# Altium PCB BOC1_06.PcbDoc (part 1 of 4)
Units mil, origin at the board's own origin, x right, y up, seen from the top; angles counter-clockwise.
Board outline 7900 x 6500 mil, 2 copper layers (Top Layer, Bottom Layer); 312 components, 413 nets, 1710 pads, 368 vias.
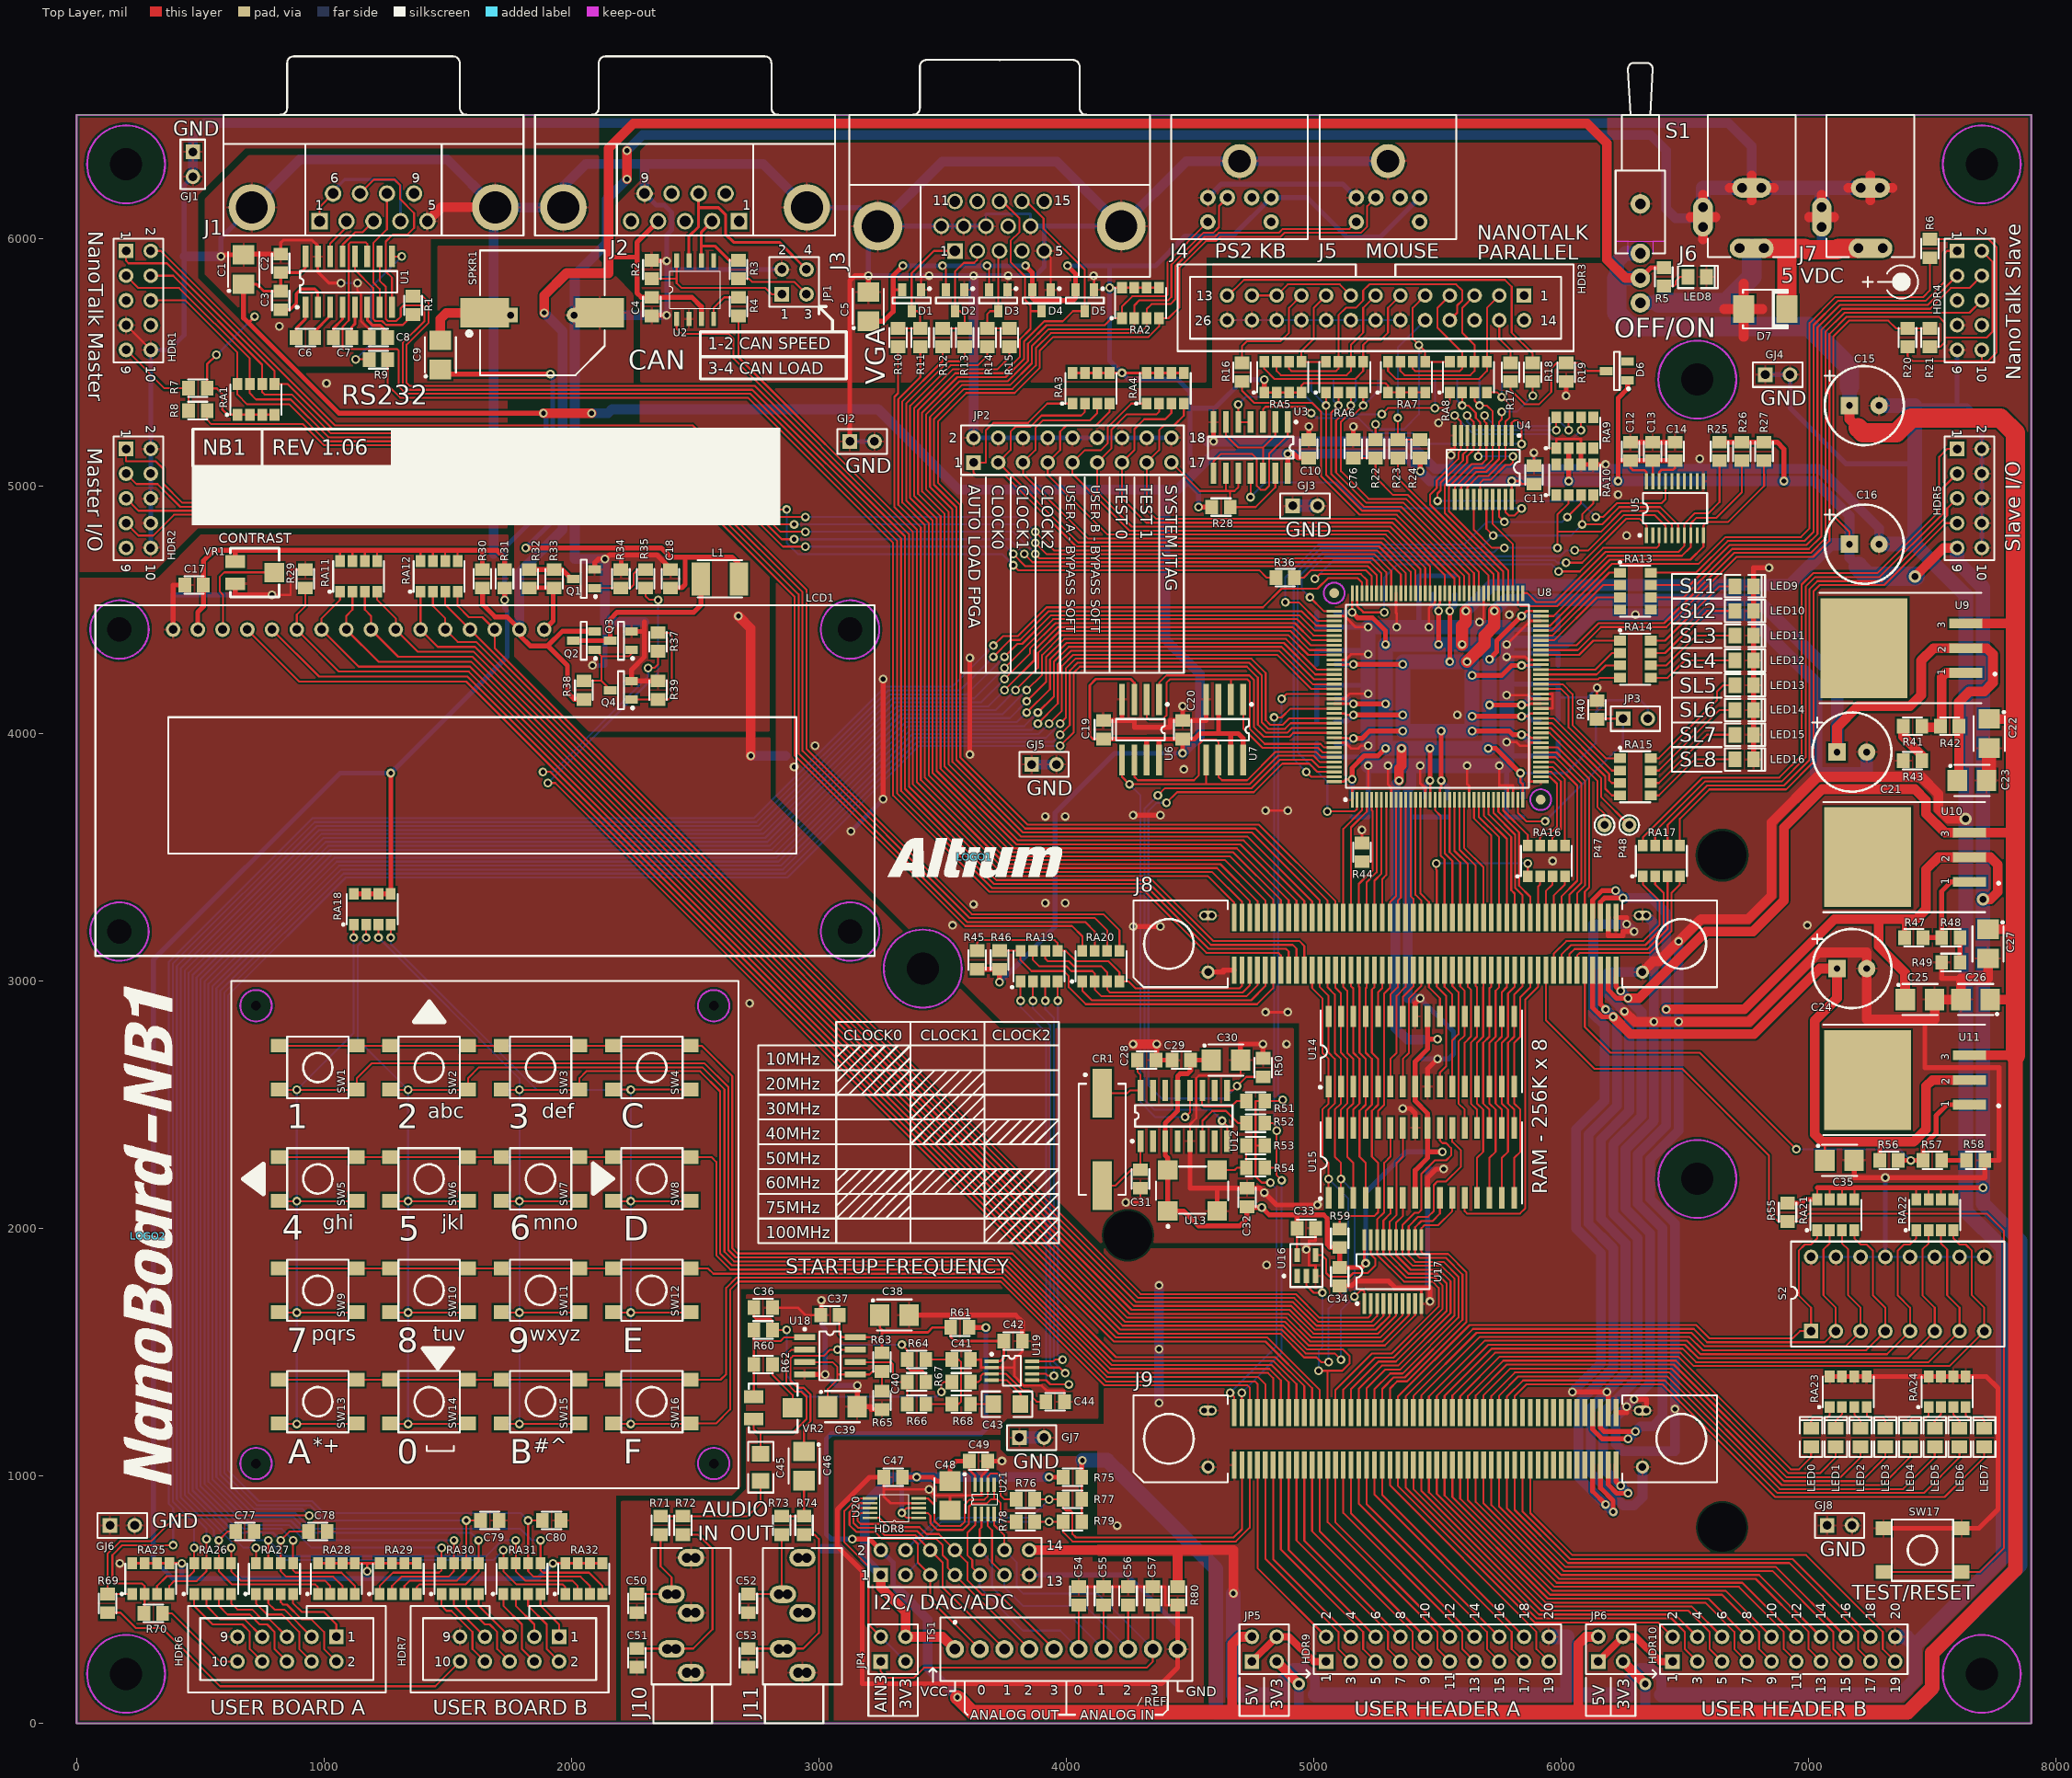
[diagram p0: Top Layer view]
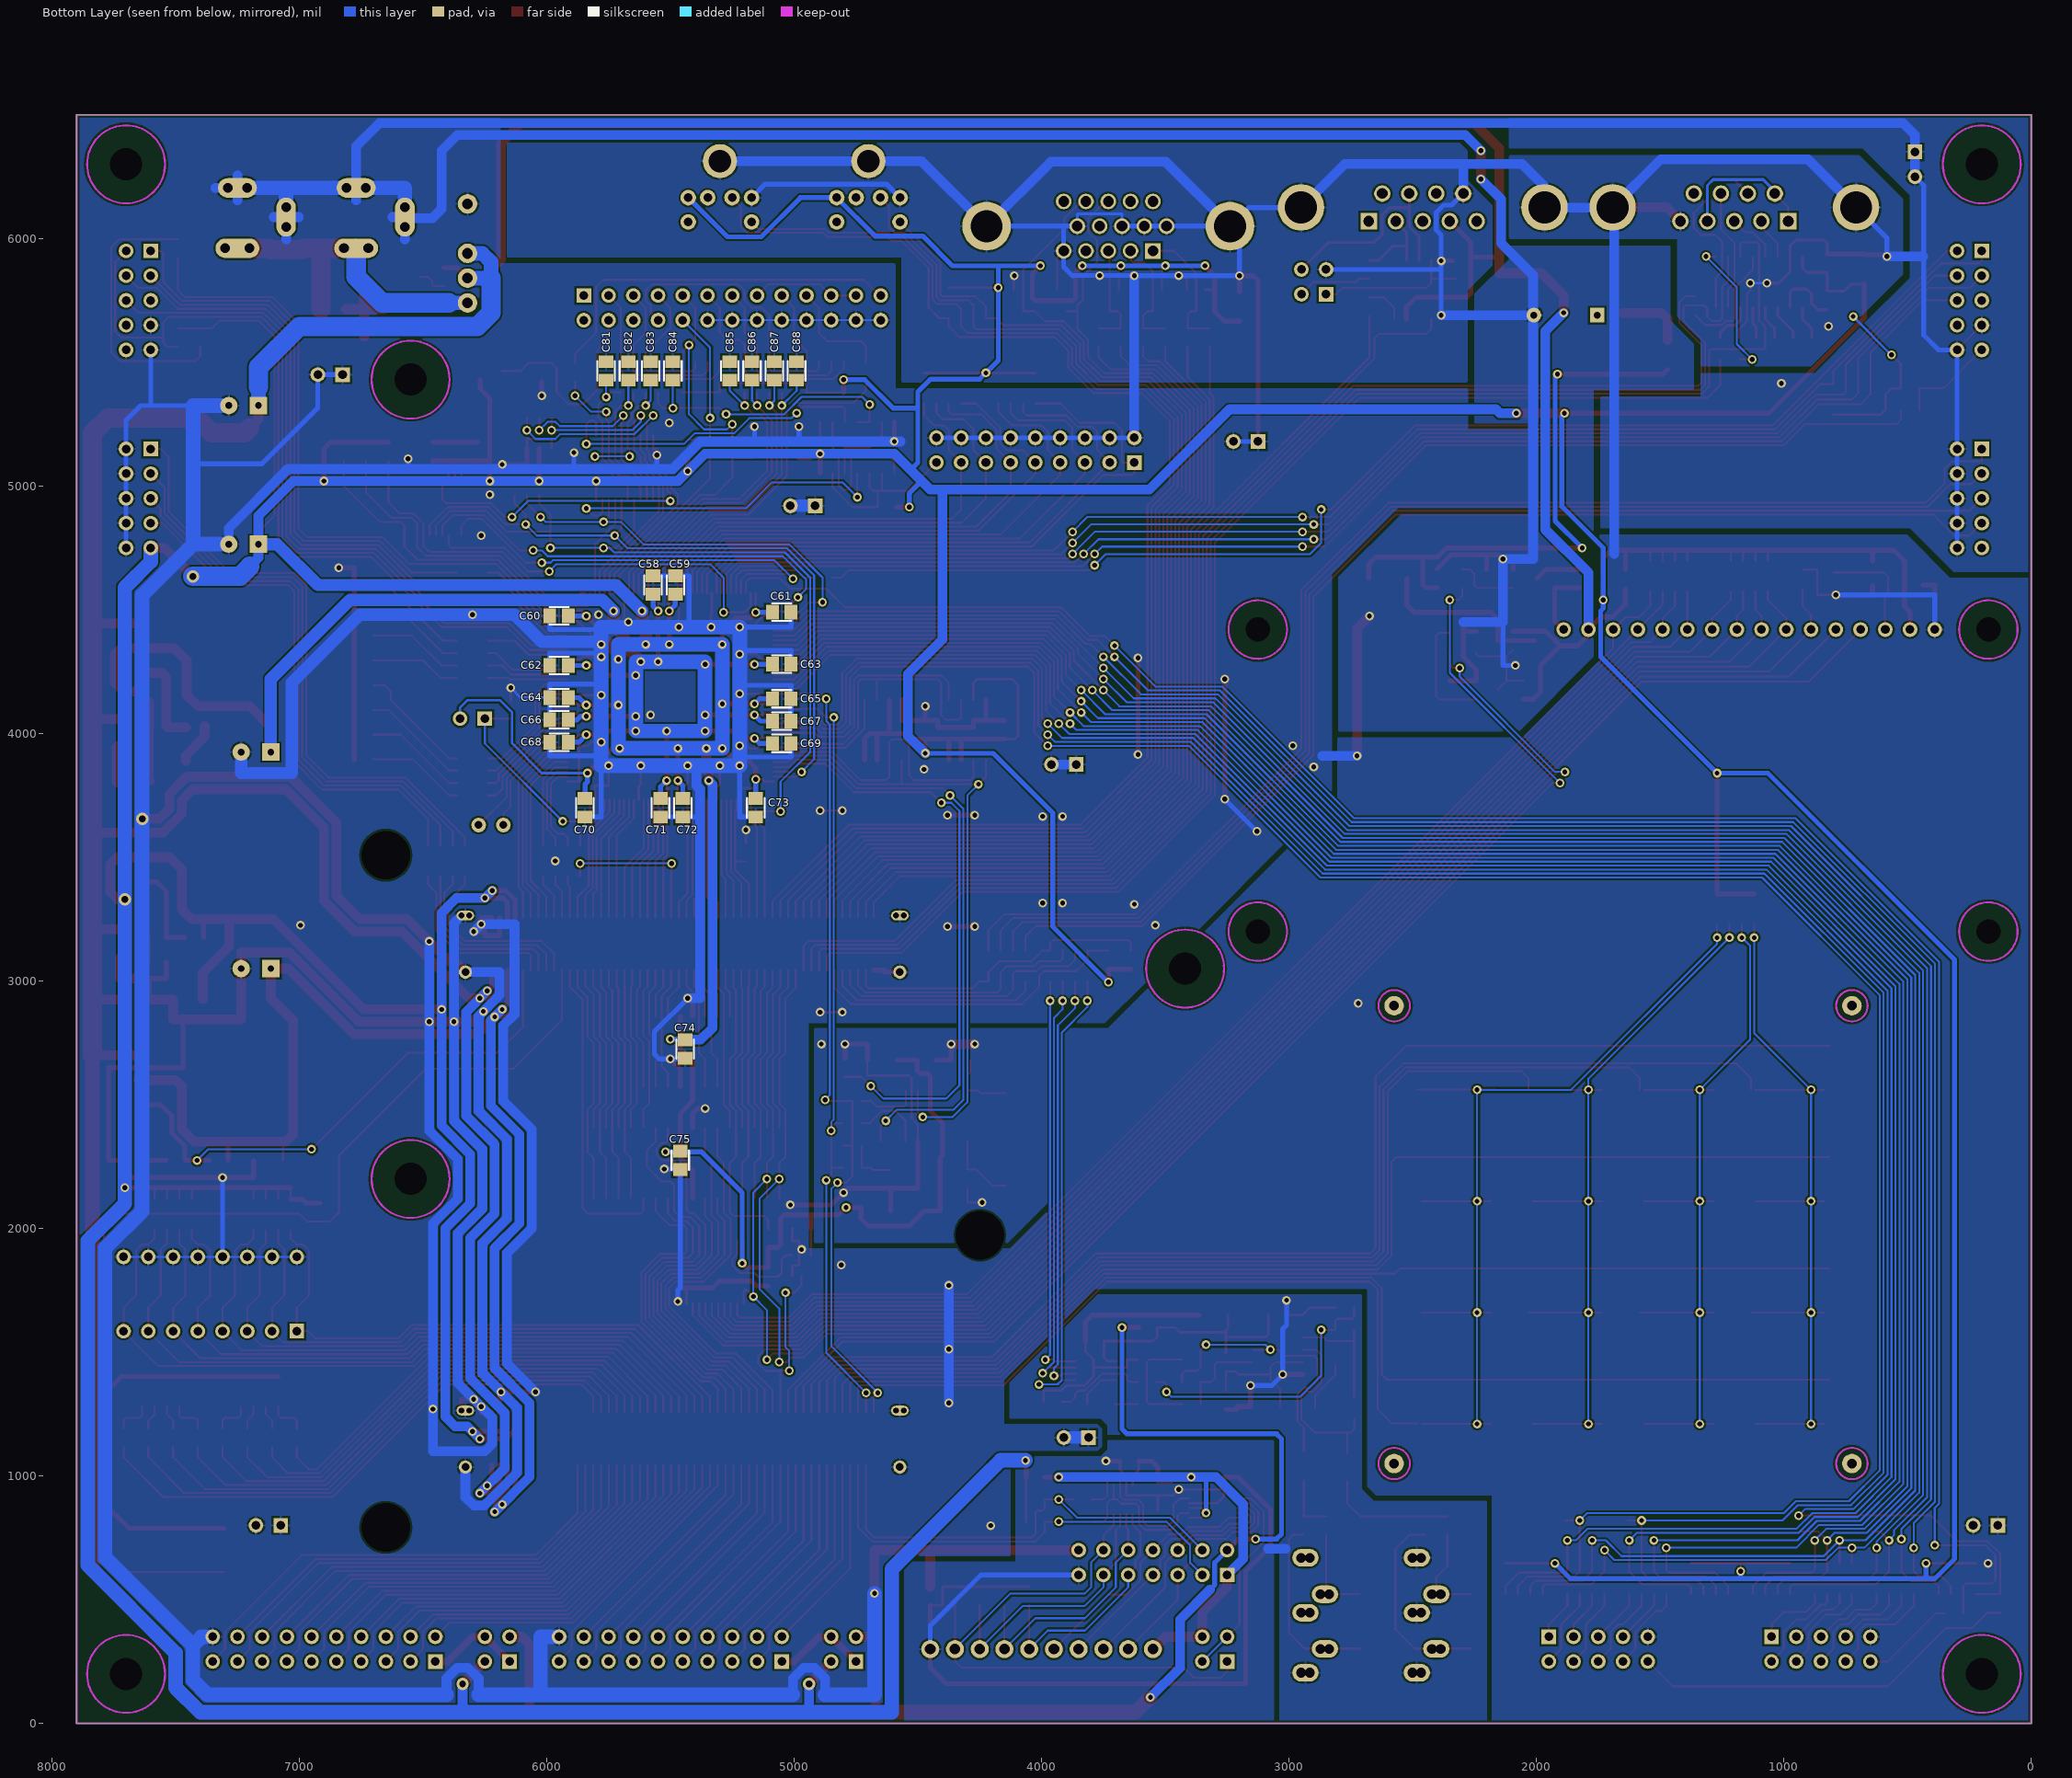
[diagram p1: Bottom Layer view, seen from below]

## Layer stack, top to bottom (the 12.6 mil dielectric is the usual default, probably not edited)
Top Layer: signal copper 1.4
Dielectric: core 12.6, FR-4, Dk 4.8
Bottom Layer: signal copper 1.4

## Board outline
0,0 7900,0 7900,6500 0,6500

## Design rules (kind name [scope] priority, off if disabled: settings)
Clearance [All] p1: gap=7.87
ComponentClearance LEDComponentClearance [HasFootprint('SMD _LED') vs HasFootprint('SMD _LED')] p1: gap=1.18 collisioncheckmode=3 verticalgap=10 showdistances=FALSE
ComponentClearance ComponentClearance_General [Not InComponent('LCD1') vs Not InComponentClass('Under_LCD1')] p2: gap=7.87 collisioncheckmode=3 verticalgap=10 showdistances=FALSE
ComponentClearance ComponentClearance_Default [All] p3 off: gap=7.87 collisioncheckmode=3 verticalgap=10 showdistances=FALSE
FabricationTestPointUsage TestPointUsage [All] p1 off: valid=0 allowmultiple=FALSE
FabricationTestpoint Testpoint [All] p1 off: side=3 testpointundercomponent=TRUE minsize=40 maxsize=100 preferedsize=60 minholesize=0 maxholesize=40 preferedholesize=32 testpointgrid=1 allowsidetop=TRUE allowsidebottom=TRUE usegrid=TRUE gridtolerance=0.01
FanoutControl Fanout_Default [All] p1: bgadir=Out bgaviamode=Centered fanoutstyle=Auto fanoutdirection=Alternating viagrid=1 // Fanout_Default (Default Rule)
FanoutControl Fanout_Small [(CompPinCount < 5)] p2: bgadir=Out bgaviamode=Centered fanoutstyle=Auto fanoutdirection=OutThenIn viagrid=1 // Fanout_Small (Default Rule)
FanoutControl Fanout_LCC [IsLCC] p4: bgadir=Out bgaviamode=Centered fanoutstyle=Auto fanoutdirection=Alternating viagrid=1 // Fanout_LCC (Default Rule)
FanoutControl Fanout_BGA [IsBGA] p5: bgadir=Out bgaviamode=Centered fanoutstyle=Auto fanoutdirection=Alternating viagrid=1 // Fanout_BGA (Default Rule)
Height MaxMinHeight [All] p1: minheight=0 maxheight=1000 prefheight=500
HoleSize HoleSize_1 [inpadclass('Connector_Slot_Pads')] p1: absolutevalues=TRUE maxlimit=1 minlimit=0 maxpercent=80.000 minpercent=20.000
HoleSize [All] p2: absolutevalues=TRUE maxlimit=200.79 minlimit=1 maxpercent=80.000 minpercent=20.000
PlaneClearance [All] p1: clearance=19.68
PlaneConnect [All] p1: planeconnectstyle=Relief reliefexpansion=19.68 reliefentries=4 reliefconductorwidth=9.84 reliefairgap=9.84
PolygonConnect [All] p1: connectstyle=Relief reliefconductorwidth=9.84 reliefentries=4 polygonreliefangle="90 Angle"
RoomDefinition BOC_Audio [InComponentClass('BOC_Audio')] p1 off: confinementstyle=ConfineIn formatcopy=TRUE lockcomponents=FALSE outline 6400,6600 6600,6600 6600,6700 6400,6700
RoomDefinition BOC_Spartan [InComponentClass('BOC_Spartan')] p2 off: confinementstyle=ConfineIn formatcopy=TRUE lockcomponents=FALSE outline 5600,6600 5800,6600 5800,6700 5600,6700
RoomDefinition BOC_Boot [InComponentClass('BOC_Boot')] p3 off: confinementstyle=ConfineIn formatcopy=TRUE lockcomponents=FALSE outline 6000,6600 6200,6600 6200,6700 6000,6700
RoomDefinition BOC_KB [InComponentClass('BOC_KB')] p4 off: confinementstyle=ConfineIn formatcopy=TRUE lockcomponents=FALSE outline 598.76,864.17 598.76,2486.22 890.13,2486.22 890.13,3087.5 1134.81,3087.5 1134.81,2684.87 6027.34,2684.87 6027.34,1365.83 6541.24,1365.83 6541.24,1093.78 2350.85,1093.78 2350.85,864.17
RoomDefinition BOC_LED_DIPSWITCH [InComponentClass('BOC_LED_DIPSWITCH')] p5 off: confinementstyle=ConfineIn formatcopy=TRUE lockcomponents=FALSE outline 6933,1621 7803,1621 7803,2703 6933,2703
RoomDefinition BOC_PWR [InComponentClass('BOC_PWR')] p6 off: confinementstyle=ConfineIn formatcopy=TRUE lockcomponents=FALSE outline 358.19,5688.19 358.19,5911.81 5462.54,5911.81 5462.54,6011.81 6438.98,6011.81 6438.98,4284.65 6785.83,4284.65 6785.83,3810.3 6800.79,3810.3 6800.79,3589.7 6785.83,3589.7 6785.83,2916.14 6749.86,2916.14 6749.86,2777.86 6235.3,2777.86 6235.3,2750.2 6108.02,2750.2 6108.02,1369.09 5884.4,1369.09 5884.4,1393.7 3465.33,1393.7 3465.33,3137.93 3464.07,3137.93 3464.07,4568.19 3078.19,4568.19 3078.19,5688.19
RoomDefinition BOC_CLK_ADJ [InComponentClass('BOC_CLK_ADJ')] p7 off: confinementstyle=ConfineIn formatcopy=TRUE lockcomponents=FALSE outline 3202,2149 4333,2149 4333,3288 3202,3288
RoomDefinition BOC_IO [InComponentClass('BOC_IO')] p8 off: confinementstyle=ConfineIn formatcopy=TRUE lockcomponents=FALSE outline 3738.19,638.19 3738.19,861.81 5361.81,861.81 6559.18,861.81 6559.18,638.19 3738.19,638.19
RoomDefinition BOC_ADC_DAC [InComponentClass('BOC_ADC_DAC')] p9 off: confinementstyle=ConfineIn formatcopy=TRUE lockcomponents=FALSE outline 2611.75,974.41 2611.75,1104.33 2675.14,1104.33 2675.14,1197.14 2827.86,1197.14 2827.86,1324.87 3022.34,1324.87 3022.34,1272.34 3199.86,1272.34 3199.86,1124.87 3827.44,1124.87 3827.44,975.14 3722.15,975.14 3722.15,975.13 3720.87,975.13 3720.87,681.3 2633.86,681.3 2633.86,974.41
RoomDefinition BOC_LCD [InComponentClass('BOC_LCD')] p10 off: confinementstyle=ConfineIn formatcopy=TRUE lockcomponents=FALSE outline 47.38,2772.38 47.38,4244.94 400.14,4244.94 400.14,4347.15 588.76,4347.15 588.76,4461.57 1294.21,4461.57 1294.21,5140.3 1439.7,5140.3 1439.7,5463.78 2124.87,5463.78 2124.87,4567.15 4534.87,4567.15 4534.87,2278.52 4805.42,2278.52 4805.42,1912.25 4706.61,1912.25 4706.61,1609.23 4529.45,1609.23 4529.45,1912.25 4483.57,1912.25 4483.57,2000.14 4352.85,2000.14 4352.85,2772.38
RoomDefinition BOC_SRAM [InComponentClass('BOC_SRAM')] p11 off: confinementstyle=ConfineIn formatcopy=TRUE lockcomponents=FALSE outline 4292.66,2155.13 4292.66,2304.86 4344.79,2304.86 4344.79,3184.03 5188.78,3184.03 5188.78,2340.2 4387.15,2340.2 4387.15,2155.13
RoomDefinition BOC_DAUGHTER [InComponentClass('BOC_DAUGHTER')] p12 off: confinementstyle=ConfineIn formatcopy=TRUE lockcomponents=FALSE outline 4059.06,1271.59 4059.06,3586.68 5525.59,3586.68 5525.59,1271.59
RoomDefinition BOC_RS232 [InComponentClass('BOC_RS232')] p13 off: confinementstyle=ConfineIn formatcopy=TRUE lockcomponents=FALSE outline 481.89,5923.03 481.89,6748.03 1718.11,6748.03 1718.11,5923.03 1307.15,5923.03 1307.15,5655.13 1199.87,5655.13 1199.87,5552.85 1194.87,5552.85 1194.87,5462.66 1045.13,5462.66 1045.13,5552.86 750.13,5552.86 750.13,5675.13 677.86,5675.13 677.86,5764.7 499.21,5764.7 499.21,5923.03
RoomDefinition BOC_CAN [InComponentClass('BOC_CAN')] p14 off: confinementstyle=ConfineIn formatcopy=TRUE lockcomponents=FALSE outline 1743.31,5921.22 1743.31,6741.14 2979.53,6741.14 2979.53,5921.22 2911.81,5921.22 2911.81,5659.13 2622.34,5659.13 2622.34,5650.14 2512.01,5650.14 2512.01,5633.6 2287.6,5633.6 2287.6,5650.14 2177.86,5650.14 2177.86,5800.13 2177.66,5800.13 2177.66,5921.22
RoomDefinition BOC_VGA_KB_MOUSE [InComponentClass('BOC_VGA_KB_MOUSE')] p15 off: confinementstyle=ConfineIn formatcopy=TRUE lockcomponents=FALSE outline 2639,5519 5463,5519 5463,6734 2639,6734
RoutingVias [All] p1: holewidth=19.68 width=35.43 viastyle="Through Hole" minholewidth=19.68 minwidth=35.43 maxholewidth=28 maxwidth=50
SilkscreenOverComponentPads [All] p1: minsilkscreentomaskgap=10
SolderMaskExpansion SolderMaskExpansion_Vias [IsVia] p1: expansion=-25.59
SolderMaskExpansion [All] p2: expansion=3.94
Width Pwr_Width [InNetClass('Power Nets')] p1: maxlimit=118.11 minlimit=7.87 preferedwidth=19.68 toplayer_prefwidth=9.84
Width [All] p2: maxlimit=59.05 minlimit=7.87 preferedwidth=7.87
16 further rules are at their usual default settings.

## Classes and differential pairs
component class Under_LCD1: Q2 Q3 Q4 R37 R38 R39 RA18
net class RAM1_DATA[0..7]: RAM1_DATA0 RAM1_DATA1 RAM1_DATA2 RAM1_DATA3 RAM1_DATA4 RAM1_DATA5 RAM1_DATA6 RAM1_DATA7
net class "Power Nets": 1V8 5V AGND GND PWR_IN VCC VCC_LCD VCCA VCCINT
net class SWR[0..3]: SWR0 SWR1 SWR2 SWR3
net class SWC[0..3]: SWC0 SWC1 SWC2 SWC3
net class SW[0..7]: SW0 SW1 SW2 SW3 SW4 SW5 SW6 SW7
net class RAM_ADDR[0..16]: RAM_ADDR0 RAM_ADDR1 RAM_ADDR2 RAM_ADDR3 RAM_ADDR4 RAM_ADDR5 RAM_ADDR6 RAM_ADDR7 RAM_ADDR8 RAM_ADDR9 RAM_ADDR10 RAM_ADDR11 RAM_ADDR12 RAM_ADDR13 RAM_ADDR14 RAM_ADDR15 RAM_ADDR16
net class RAM_ADDR[0..1]: RAM_ADDR0 RAM_ADDR1
net class RAM0_DATA[0..7]: RAM0_DATA0 RAM0_DATA1 RAM0_DATA2 RAM0_DATA3 RAM0_DATA4 RAM0_DATA5 RAM0_DATA6 RAM0_DATA7
net class MODE_[1..8]: MODE_1 MODE_2 MODE_3 MODE_4 MODE_5 MODE_6 MODE_7 MODE_8
net class JIOB[0..3]: JIOB0 JIOB1 JIOB2 JIOB3
net class JIOA[0..3]: JIOA0 JIOA1 JIOA2 JIOA3
net class IO[0..35]: IO0 IO1 IO2 IO3 IO4 IO5 IO6 IO7 IO8 IO9 IO10 IO11 IO12 IO13 IO14 IO15 IO16 IO17 IO18 IO19 IO20 IO21 IO22 IO23 IO24 IO25 IO26 IO27 IO28 IO29 IO30 IO31 IO32 IO33 IO34 IO35
pad class Connector_Slot_Pads: J6-1 J6-2 J6-3 J7-1 J7-2 J7-3 J8-MH2 J8-MH4 J9-MH2 J9-MH4 J10-1 J10-2 J10-3 J10-4 J10-5 J11-1 J11-2 J11-3 J11-4 J11-5
component class BOC_ADC_DAC: C47 C48 C49 C54 C55 C56 C57 HDR8 JP4 R75 R76 R77 R78 R79 R80 TS1 U20 U21
component class BOC_Audio: C36 C37 C38 C39 C40 C41 C42 C43 C44 C45 C46 C50 C51 C52 C53 J10 J11 R45 R46 R60 R61 R62 R63 R64 R65 R66 R67 R68 R71 R72 R73 R74 RA19 U18 U19 VR2
component class BOC_CAN: C4 J2 JP1 R2 R3 R4 U2
component class BOC_CLK_ADJ: C28 C29 C30 C31 C32 CR1 R50 R51 R52 R53 R54 U12 U13
component class BOC_DAUGHTER: J8 J9
component class BOC_IO: HDR9 HDR10 JP5 JP6
component class BOC_KB: R55 RA18 SW1 SW2 SW3 SW4 SW5 SW6 SW7 SW8 SW9 SW10 SW11 SW12 SW13 SW14 SW15 SW16 SW17
component class BOC_LCD: C9 C17 C18 C33 C34 L1 LCD1 Q1 Q2 Q3 Q4 R29 R30 R31 R32 R33 R34 R35 R37 R38 R39 RA11 RA12 SPKR1 U16 U17 VR1
component class BOC_LED_DIPSWITCH: LED0 LED1 LED2 LED3 LED4 LED5 LED6 LED7 RA21 RA22 RA23 RA24 S2
component class BOC_PWR: C15 C16 C21 C22 C23 C24 C25 C26 C27 C35 D7 GJ1 GJ2 GJ3 GJ4 GJ5 GJ6 GJ7 GJ8 J6 J7 R41 R42 R43 R47 R48 R49 R56 R57 R58 S1 U9 U10 U11
component class BOC_RS232: C1 C2 C3 C6 C7 C8 J1 R1 R9 U1
component class BOC_SRAM: C74 C75 R59 U14 U15
component class BOC_VGA_KB_MOUSE: C5 D1 D2 D3 D4 D5 J3 J4 J5 R10 R11 R12 R13 R14 R15 RA2
component class BOC_Boot: C10 C11 C12 C13 C14 C58 C59 C60 C61 C62 C63 C64 C65 C66 C67 C68 C69 C70 C71 C72 C73 C76 C81 C82 C83 C84 C85 C86 C87 C88 D6 HDR3 JP2 JP3 R16 R17 R18 R19 R22 R23 R24 R25 R26 R27 R28 R40 RA3 RA4 RA5 RA6 RA7 RA8 RA9 RA10 U3 U4 U5
component class BOC_Spartan: C19 C20 C77 C78 C79 C80 HDR1 HDR2 HDR4 HDR5 HDR6 HDR7 LED8 LED9 LED10 LED11 LED12 LED13 LED14 LED15 LED16 R5 R6 R7 R8 R20 R21 R36 R44 R69 R70 RA1 RA13 RA14 RA15 RA16 RA17 RA20 RA25 RA26 RA27 RA28 RA29 RA30 RA31 RA32 U6 U7 U8

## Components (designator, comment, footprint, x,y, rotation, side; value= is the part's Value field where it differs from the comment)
C1 "10uF" MCCT-B 675,5875 r90 top
C2 "100nF" CC2012-0805 825,5900 r90 top
C3 "100nF" CC2012-0805 825,5750 r270 top
C4 "100nF" CC2012-0805 2325,5725 r270 top
C5 "10uF" MCCT-B 3200,5725 r90 top
C6 "100nF" CC2012-0805 925,5600 r0 top
C7 "100nF" CC2012-0805 1075,5600 r0 top
C8 "100nF" CC2012-0805 1220,5600 r180 top
C9 "10uF" MCCT-B 1470,5530 r90 top
C10 "100nF" CC2012-0805 4980,5150 r90 top
C11 "100nF" CC2012-0805 5890,5045 r90 top
C12 "100nF" CC2012-0805 6280,5140 r270 top
C13 "100nF" CC2012-0805 6370,5140 r270 top
C14 "100nF" CC2012-0805 6460,5140 r270 top
C15 "470uF 16V" RB8/3.5 7225,5325 r90 top
C16 "470uF 16V" RB8/3.5 7225,4765 r90 top
C17 "100nF" CC2012-0805 475,4600 r180 top
C18 "22nF" CC2012-0805 2400,4625 r90 top
C19 "100nF" CC2012-0805 4150,4015 r270 top
C20 "100nF" CC2012-0805 4470,4015 r90 top
C21 "470uF 16V" RB8/3.5 7175,3925 r90 top
C22 "10uF" MCCT-B 7730,4000 r270 top
C23 "10uF" MCCT-B 7660,3810 r0 top
C24 "470uF 16V" RB8/3.5 7175,3050 r90 top
C25 "10uF" MCCT-B 7450,2925 r0 top
C26 "10uF" MCCT-B 7675,2925 r180 top
C27 "10uF" MCCT-B 7725,3150 r270 top
C28 "Do Not Install" CC2012-0805 4325,2680 r0 top
C29 "100nF" CC2012-0805 4465,2680 r180 top
C30 "10uF" MCCT-B 4645,2680 r0 top
C31 "Do Not Install" CC2012-0805 4300,2200 r270 top
C32 "100nF" CC2012-0805 4730,2125 r90 top
C33 "100nF" CC2012-0805 4970,2000 r0 top
C34 "100nF" CC2012-0805 5105,1805 r270 top
C35 "10uF" MCCT-B 7125,2275 r0 top
C36 "22nF" CC2012-0805 2775,1680 r0 top
C37 "100nF" CC2012-0805 3045,1650 r0 top
C38 "10uF" MCCT-B 3305,1650 r0 top
C39 "10uF" MCCT-B 3095,1280 r0 top
C40 "470pF" CC2012-0805 3395,1380 r0 top
C41 "4700pF" CC2012-0805 3575,1470 r0 top
C42 "100nF" CC2012-0805 3785,1545 r0 top
C43 "1uF" C3216-1206 3760,1290 r0 top
C44 "4700pF" CC2012-0805 3955,1300 r0 top
C45 "1uF" C3216-1206 2765,1035 r90 top
C46 "10uF" MCCT-B 2940,1040 r270 top
C47 "100nF" CC2012-0805 3300,995 r180 top
C48 "10uF" MCCT-B 3530,920 r270 top
C49 "100nF" CC2012-0805 3645,1060 r0 top
C50 "220pF" CC2012-0805 2265,485 r270 top
C51 "220pF" CC2012-0805 2265,265 r270 top
C52 "220pF" CC2012-0805 2715,485 r270 top
C53 "220pF" CC2012-0805 2715,265 r270 top
C54 "100pF" CC2012-0805 4050,515 r90 top
C55 "100pF" CC2012-0805 4150,515 r90 top
C56 "100pF" CC2012-0805 4250,515 r90 top
C57 "100pF" CC2012-0805 4350,515 r90 top
C58 "100nF" CC2012-0805 5570,4600 r90 bottom
C59 "100nF" CC2012-0805 5480,4600 r90 bottom
C60 "100nF" CC2012-0805 5950,4475 r0 bottom
C61 "100nF" CC2012-0805 5050,4490 r180 bottom
C62 "100nF" CC2012-0805 5950,4275 r0 bottom
C63 "100nF" CC2012-0805 5050,4280 r180 bottom
C64 "100nF" CC2012-0805 5950,4145 r0 bottom
C65 "100nF" CC2012-0805 5050,4140 r180 bottom
C66 "100nF" CC2012-0805 5950,4055 r0 bottom
C67 "100nF" CC2012-0805 5050,4050 r180 bottom
C68 "100nF" CC2012-0805 5950,3965 r0 bottom
C69 "100nF" CC2012-0805 5050,3960 r180 bottom
C70 "100nF" CC2012-0805 5845,3700 r270 bottom
C71 "100nF" CC2012-0805 5540,3700 r270 bottom
C72 "100nF" CC2012-0805 5450,3700 r270 bottom
C73 "100nF" CC2012-0805 5155,3700 r270 bottom
C74 "100nF" CC2012-0805 5440,2725 r270 bottom
C75 "100nF" CC2012-0805 5460,2275 r270 bottom
C76 "100pF" CC2012-0805 5160,5150 r90 top
C77 "1nF" CC2012-0805 680,775 r0 top
C78 "1nF" CC2012-0805 975,775 r0 top
C79 "1nF" CC2012-0805 1670,820 r0 top
C80 "1nF" CC2012-0805 1920,820 r0 top
C81 "1nF" CC2012-0805 5760,5465 r90 bottom
C82 "1nF" CC2012-0805 5670,5465 r90 bottom
C83 "1nF" CC2012-0805 5580,5465 r90 bottom
C84 "1nF" CC2012-0805 5490,5465 r90 bottom
C85 "1nF" CC2012-0805 5260,5465 r90 bottom
C86 "1nF" CC2012-0805 5170,5465 r90 bottom
C87 "1nF" CC2012-0805 5080,5465 r90 bottom
C88 "1nF" CC2012-0805 4990,5465 r90 bottom
CR1 "QC49/SMD" QC49/SMD 4145,2360 r270 top
D1 "BAS40-04" SO-G3 3375,5750 r180 top
D2 "BAS40-04" SO-G3 3550,5750 r180 top
D3 "BAS40-04" SO-G3 3725,5750 r180 top
D4 "BAS40-04" SO-G3 3900,5750 r180 top
D5 "BAS40-04" SO-G3 4075,5750 r180 top
D6 "BAS40" SO-G3 6225,5465 r90 top
D7 "SMBJ5341B" DO214 6825,5715 r0 top
GJ1 "Header 2" HDR1X2 470,6350 r270 top
GJ2 "Header 2" HDR1X2 3125,5180 r0 top
GJ3 "Header 2" HDR1X2 4915,4920 r0 top
GJ4 "Header 2" HDR1X2 6825,5450 r0 top
GJ5 "Header 2" HDR1X2 3860,3875 r0 top
GJ6 "Header 2" HDR1X2 135,800 r0 top
GJ7 "Header 2" HDR1X2 3810,1155 r0 top
GJ8 "Header 2" HDR1X2 7075,800 r0 top
HDR1 "Header 5X2" HDR2X5 200,5950 r270 top
HDR2 "Header 5X2" HDR2X5 200,5150 r270 top
HDR3 "70246-2622" HDR2X13_CEN_LP 5850,5770 r180 top
HDR4 "Header 5X2" HDR2X5 7600,5950 r270 top
HDR5 "Header 5X2" HDR2X5 7600,5150 r270 top
HDR6 "70246-1022" HDR2X5_LP 1050,350 r180 top
HDR7 "70246-1022" HDR2X5_LP 1950,350 r180 top
HDR8 "Header 7X2" HDR2X7 3250,600 r0 top
HDR9 "Header 10X2" HDR2X10 5050,250 r0 top
HDR10 "Header 10X2" HDR2X10 6450,250 r0 top
J1 "DB9 Female" DSUB1.385-2H9 1200,6500 r0 top
J2 "D Connector 9_MALE" DSUB1.9_MALE 2622.88,6181.89 r0 top
J3 "Dsub-15-Female-HD" DB15-VGA-Female 3550,5950 r0 top
J4 "8918-P6" PS2-6PIN 4700,6500 r0 top
J5 "8918-P6" PS2-6PIN 5300,6500 r0 top
J6 "KLD-0202-B" KLD-0202 6770,6500 r270 top
J7 "KLD-0202-B" KLD-0202 7250,6500 r270 top
J8 "53751-1009" 53751 5450,3150 r0 top locked
J9 "53751-1009" 53751 5450,1150 r0 top locked
J10 "ST-3150-5N" ST-3150-5N 2450,0 r180 top
J11 "ST-3150-5N" ST-3150-5N 2900,0 r180 top
JP1 "Header 2X2" HDR2X2 2850,5775 r0 top
JP2 "Header 9X2" HDR2X9 3625,5095 r0 top
JP3 "Header 2" HDR1X2 6250,4060 r0 top
JP4 "Header 2X2" HDR2X2_B 3250,250 r0 top
JP5 "Header 2X2" HDR2X2_B 4750,250 r0 top
JP6 "Header 2X2" HDR2X2_B 6150,250 r0 top
L1 "330uH" CC4532-1812 2600,4625 r0 top
LCD1 "162A" 162A 75.04,3101.1 r0 top locked
LED0 "HSMH-C170" "SMD _LED" 7010,1155 r270 top
LED1 "HSMH-C170" "SMD _LED" 7110,1155 r270 top
LED2 "HSMH-C170" "SMD _LED" 7210,1155 r270 top
LED3 "HSMH-C170" "SMD _LED" 7310,1155 r270 top
LED4 "HSMH-C170" "SMD _LED" 7410,1155 r270 top
LED5 "HSMH-C170" "SMD _LED" 7510,1155 r270 top
LED6 "HSMH-C170" "SMD _LED" 7610,1155 r270 top
LED7 "HSMH-C170" "SMD _LED" 7710,1155 r270 top
LED8 "HSMH-C170" "SMD _LED" 6550,5845 r180 top
LED9 "HSMH-C170" "SMD _LED" 6740,4595 r180 top
LED10 "HSMH-C170" "SMD _LED" 6740,4495 r180 top
LED11 "HSMH-C170" "SMD _LED" 6740,4395 r180 top
LED12 "HSMH-C170" "SMD _LED" 6740,4295 r180 top
LED13 "HSMH-C170" "SMD _LED" 6740,4195 r180 top
LED14 "HSMH-C170" "SMD _LED" 6740,4095 r180 top
LED15 "HSMH-C170" "SMD _LED" 6740,3995 r180 top
LED16 "HSMH-C170" "SMD _LED" 6740,3895 r180 top
LOGO1 "Altium_Logo" Altium_Logo 3630,3500 r0 top
LOGO2 "NanoBoard1_LOGO" NanoBoard1_LOGO 290,1970 r90 top
Q1 "2N7002" SO-G3 2050,4625 r90 top
Q2 "BSS84" SO-G3 2050,4375 r90 top
Q3 "2N7002" SO-G3 2200,4375 r90 top
Q4 "2N7002" SO-G3 2200,4175 r90 top
R1 "100R" CC2012-0805 1360,5730 r270 top
R2 "15K" CC2012-0805 2325,5875 r270 top
R3 "120R" CC2012-0805 2675,5875 r90 top
R4 "270R" CC2012-0805 2675,5725 r90 top
R5 "270R" CC2012-0805 6415,5845 r270 top
R6 "1K" CC2012-0805 7490,5960 r90 top
R7 "1K" CC2012-0805 490,5395 r180 top
R8 "1K" CC2012-0805 490,5305 r0 top
R9 "100R" CC2012-0805 1220,5510 r180 top
R10 "680R" CC2012-0805 3320,5600 r90 top
R11 "330R" CC2012-0805 3410,5600 r90 top
R12 "680R" CC2012-0805 3500,5600 r90 top
R13 "330R" CC2012-0805 3590,5600 r90 top
R14 "680R" CC2012-0805 3680,5600 r90 top
R15 "330R" CC2012-0805 3770,5600 r90 top
R16 "47R" CC2012-0805 4710,5460 r270 top
R17 "100R" CC2012-0805 5795,5460 r270 top
R18 "47R" CC2012-0805 5885,5460 r270 top
R19 "4K7" CC2012-0805 6020,5460 r270 top
R20 "1K" CC2012-0805 7400,5600 r270 top
R21 "4K7" CC2012-0805 7490,5600 r270 top
R22 "1K" CC2012-0805 5250,5150 r270 top
R23 "1K" CC2012-0805 5340,5150 r270 top
R24 "1K" CC2012-0805 5430,5150 r270 top
R25 "4K7" CC2012-0805 6640,5140 r270 top
R26 "4K7" CC2012-0805 6730,5140 r270 top
R27 "4K7" CC2012-0805 6820,5140 r270 top
R28 "4K7" CC2012-0805 4625,4915 r180 top
R29 "4K7" CC2012-0805 925,4625 r90 top
R30 "0R" CC2012-0805 1640,4625 r90 top
R31 "0R" CC2012-0805 1730,4625 r90 top
R32 "68R" CC2012-0805 1830,4625 r90 top
R33 "68R" CC2012-0805 1930,4625 r90 top
R34 "10K" CC2012-0805 2200,4625 r270 top
R35 "560R" CC2012-0805 2300,4625 r90 top
R36 "100R" CC2012-0805 4885,4630 r0 top
R37 "560R" CC2012-0805 2350,4370 r90 top
R38 "4K7" CC2012-0805 2050,4175 r90 top
R39 "10K" CC2012-0805 2350,4175 r90 top
R40 "1K" CC2012-0805 6145,4095 r270 top
R41 "47R" CC2012-0805 7420,4030 r180 top
R42 "120R" CC2012-0805 7570,4030 r180 top
R43 "5R6" CC2012-0805 7420,3890 r180 top
R44 "1K" CC2012-0805 5195,3520 r270 top
R45 "4K7" CC2012-0805 3640,3085 r270 top
R46 "4K7" CC2012-0805 3730,3085 r270 top
R47 "120R" CC2012-0805 7425,3175 r0 top
R48 "100R" CC2012-0805 7575,3175 r0 top
R49 "100R" CC2012-0805 7575,3075 r0 top
R50 "1K" CC2012-0805 4795,2650 r90 top
R51 "33R" CC2012-0805 4765,2515 r0 top
R52 "33R" CC2012-0805 4765,2425 r0 top
R53 "33R" CC2012-0805 4765,2335 r0 top
R54 "33R" CC2012-0805 4765,2245 r0 top
R55 "4K7" CC2012-0805 6915,2065 r270 top
R56 "120R" CC2012-0805 7325,2275 r0 top
R57 "47R" CC2012-0805 7500,2275 r0 top
R58 "5R6" CC2012-0805 7675,2275 r0 top
R59 "4K7" CC2012-0805 5105,1960 r90 top
R60 "470R" CC2012-0805 2775,1590 r0 top
R61 "10R" CC2012-0805 3570,1600 r180 top
R62 "1K" CC2012-0805 2775,1450 r180 top
R63 "10K" CC2012-0805 3255,1460 r90 top
R64 "4K7" CC2012-0805 3395,1470 r0 top
R65 "10K" CC2012-0805 3255,1305 r90 top
R66 "18K" CC2012-0805 3395,1290 r180 top
R67 "1K8" CC2012-0805 3575,1380 r0 top
R68 "4K7" CC2012-0805 3575,1290 r0 top
R69 "100R" CC2012-0805 125,485 r270 top
R70 "100R" CC2012-0805 310,445 r0 top
R71 "10K" CC2012-0805 2360,800 r90 top
R72 "10K" CC2012-0805 2450,800 r90 top
R73 "560R" CC2012-0805 2850,800 r90 top
R74 "560R" CC2012-0805 2940,800 r90 top
R75 "4R7" CC2012-0805 4025,995 r0 top
R76 "100R" CC2012-0805 3835,905 r180 top
R77 "4K7" CC2012-0805 4025,905 r180 top
R78 "100R" CC2012-0805 3835,815 r180 top
R79 "4K7" CC2012-0805 4025,815 r180 top
R80 "0R" CC2012-0805 4450,515 r270 top
RA1 "4K7" MNR34 725,5350 r90 top
RA2 "4K7" MNR34 4300,5740 r90 top
RA3 "4K7" MNR34 4100,5395 r90 top
RA4 "4K7" MNR34 4400,5395 r90 top
RA5 "4K7" MNR34 4875,5440 r90 top
RA6 "100R" MNR34 5125,5440 r90 top
RA7 "4K7" MNR34 5375,5440 r90 top
RA8 "100R" MNR34 5625,5440 r90 top
RA9 "4K7" MNR34 6055,5215 r90 top
RA10 "4K7" MNR34 6055,5025 r90 top
RA11 "4K7" MNR34 1140,4635 r90 top
RA12 "4K7" MNR34 1465,4635 r90 top
RA13 "100R" MNR34 6300,4575 r0 top
RA14 "270R" MNR34 6300,4300 r0 top
RA15 "270R" MNR34 6300,3825 r0 top
RA16 "100R" MNR34 5940,3485 r90 top
RA17 "100R" MNR34 6405,3485 r90 top
RA18 "4K7" MNR34 1195,3290 r90 top
RA19 "100R" MNR34 3890,3060 r90 top
RA20 "100R" MNR34 4140,3060 r90 top
RA21 "4K7" MNR34 7110,2055 r90 top
RA22 "4K7" MNR34 7510,2055 r90 top
RA23 "270R" MNR34 7160,1340 r90 top
RA24 "270R" MNR34 7560,1340 r90 top
RA25 "4K7" MNR34 300,585 r90 top
RA26 "100R" MNR34 550,585 r90 top
RA27 "100R" MNR34 800,585 r90 top
RA28 "4K7" MNR34 1050,585 r90 top
RA29 "4K7" MNR34 1300,585 r90 top
RA30 "100R" MNR34 1550,585 r90 top
RA31 "100R" MNR34 1800,585 r90 top
RA32 "4K7" MNR34 2050,585 r90 top
S1 "TL36WW050" TL36WW15050 6320,5940 r0 top
S2 "A6ER-8104" DIP-16-KEY 7010,1585 r0 top
SPKR1 "ABSM-1574-05 Transducer" ABSM-1574 1650,5700 r0 top
SW1 "DTSM-61-NR" B3FS_SWITCH 975,2650 r180 top
SW2 "DTSM-61-NR" B3FS_SWITCH 1425,2650 r180 top
SW3 "DTSM-61-NR" B3FS_SWITCH 1875,2650 r180 top
SW4 "DTSM-61-NR" B3FS_SWITCH 2325,2650 r180 top
SW5 "DTSM-61-NR" B3FS_SWITCH 975,2200 r180 top
SW6 "DTSM-61-NR" B3FS_SWITCH 1425,2200 r180 top
SW7 "DTSM-61-NR" B3FS_SWITCH 1875,2200 r180 top
SW8 "DTSM-61-NR" B3FS_SWITCH 2325,2200 r180 top
SW9 "DTSM-61-NR" B3FS_SWITCH 975,1750 r180 top
SW10 "DTSM-61-NR" B3FS_SWITCH 1425,1750 r180 top
SW11 "DTSM-61-NR" B3FS_SWITCH 1875,1750 r180 top
SW12 "DTSM-61-NR" B3FS_SWITCH 2325,1750 r180 top
SW13 "DTSM-61-NR" B3FS_SWITCH 975,1300 r180 top
SW14 "DTSM-61-NR" B3FS_SWITCH 1425,1300 r180 top
SW15 "DTSM-61-NR" B3FS_SWITCH 1875,1300 r180 top
SW16 "DTSM-61-NR" B3FS_SWITCH 2325,1300 r180 top
SW17 "DTSM-61-NR" B3FS_SWITCH 7460,700 r0 top
TS1 "TS10" TS2.54x10 3550,300 r90 top
U1 "MAX3232CSE" SO-G16 1100,5825 r0 top
U2 "MCP2551" SOIC8 2425,5675 r90 top
U3 "SN74LVC00AD" SO-G14/Y2.2 4745,5155 r180 top
U4 "SN74LVC244ADB" SSO-G20/P.65 5685,5075 r180 top
U5 "XCF01SVO20C" VO20 6460,4910 r0 top
U6 "M25P80-VMW6" SO8_MW/SO8_MN 4300,4015 r180 top
U7 "M25P80-VMW6" SO8_MW/SO8_MN 4640,4015 r180 top
U8 "XC2S100E-6TQ144C" TQ144 5500,4150 r90 top
U9 "LM1084IS-ADJ" TO-263 7635,4245 r90 top
U10 "LM1084IS-ADJ" TO-263 7650,3400 r90 top
U11 "LM1084IS-ADJ" TO-263 7650,2500 r90 top
U12 "ICS307M-02" SO-G16 4475,2455 r0 top
U13 "QSMO_4200" QSMO_4200 4410,2055 r0 top
U14 "IDT71V124SA15Y" SO-J32 5435,2715 r0 top
U15 "IDT71V124SA15Y" SO-J32 5435,2265 r0 top
U16 "SN74LVC1G04DBV" SO-G5/P.95 4970,1850 r0 top
U17 "SN74LVC245ADB" SSO-G20/P.65 5320,1825 r0 top
U18 "OPA2340UA" SO-G8 3045,1485 r270 top
U19 "MAX1104EUA" TSSO3x5-G8/X.35 3780,1425 r270 top
U20 "MAX5841MEUB" USOP10 3305,870 r180 top
U21 "MAX1037EKA-T" SOT23_8 3670,905 r90 top
VR1 "20K" POT4MM-2 720,4650 r0 top
VR2 "100K" POT4MM-2 2815,1275 r0 top

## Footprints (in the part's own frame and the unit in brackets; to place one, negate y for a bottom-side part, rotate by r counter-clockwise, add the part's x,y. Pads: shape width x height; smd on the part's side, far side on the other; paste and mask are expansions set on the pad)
162A [mm]
  round 1.5 hole 0.9: 1(8,33.5) 2(10.54,33.5) 3(13.08,33.5) 4(15.62,33.5) 5(18.16,33.5) 6(20.7,33.5) 7(23.24,33.5) 8(25.78,33.5) 9(28.32,33.5) 10(30.86,33.5) 11(33.4,33.5) 12(35.94,33.5) 13(38.48,33.5) 14(41.02,33.5) 15(43.56,33.5) 16(46.1,33.5)
  round 2.3 hole 2.5 unplated: M1(2.5,33.5) M2(77.5,33.5) M3(2.5,2.5) M4(77.5,2.5)
  Keep-Out Layer circle w0.2: c2.5,33.5 r3
  Keep-Out Layer circle w0.2: c2.5,2.5 r3
  Keep-Out Layer circle w0.2: c77.5,2.5 r3
  Keep-Out Layer circle w0.2: c77.5,33.5 r3
  silkscreen extent 0,0 80,36
53751 [mm] "Connector; Docking Station, Plug; 100 Position; Vertical"
  rect 0.5x2.8 smd: 1(-19.6,-2.7) 2(-19.6,2.7) 3(-18.8,-2.7) 4(-18.8,2.7) 5(-18,-2.7) 6(-18,2.7) 7(-17.2,-2.7) 8(-17.2,2.7) 9(-16.4,-2.7) 10(-16.4,2.7) 11(-15.6,-2.7) 12(-15.6,2.7) 13(-14.8,-2.7) 14(-14.8,2.7) 15(-14,-2.7) 16(-14,2.7) 17(-13.2,-2.7) 18(-13.2,2.7) 19(-12.4,-2.7) 20(-12.4,2.7) 21(-11.6,-2.7) 22(-11.6,2.7) 23(-10.8,-2.7) 24(-10.8,2.7) 25(-10,-2.7) 26(-10,2.7) 27(-9.2,-2.7) 28(-9.2,2.7) 29(-8.4,-2.7) 30(-8.4,2.7) 31(-7.6,-2.7) 32(-7.6,2.7) 33(-6.8,-2.7) 34(-6.8,2.7) 35(-6,-2.7) 36(-6,2.7) 37(-5.2,-2.7) 38(-5.2,2.7) 39(-4.4,-2.7) 40(-4.4,2.7) 41(-3.6,-2.7) 42(-3.6,2.7) 43(-2.8,-2.7) 44(-2.8,2.7) 45(-2,-2.7) 46(-2,2.7) 47(-1.2,-2.7) 48(-1.2,2.7) 49(-0.4,-2.7) 50(-0.4,2.7) 51(0.4,-2.7) 52(0.4,2.7) 53(1.2,-2.7) 54(1.2,2.7) 55(2,-2.7) 56(2,2.7) 57(2.8,-2.7) 58(2.8,2.7) 59(3.6,-2.7) 60(3.6,2.7) 61(4.4,-2.7) 62(4.4,2.7) 63(5.2,-2.7) 64(5.2,2.7) 65(6,-2.7) 66(6,2.7) 67(6.8,-2.7) 68(6.8,2.7) 69(7.6,-2.7) 70(7.6,2.7) 71(8.4,-2.7) 72(8.4,2.7) 73(9.2,-2.7) 74(9.2,2.7) 75(10,-2.7) 76(10,2.7) 77(10.8,-2.7) 78(10.8,2.7) 79(11.6,-2.7) 80(11.6,2.7) 81(12.4,-2.7) 82(12.4,2.7) 83(13.2,-2.7) 84(13.2,2.7) 85(14,-2.7) 86(14,2.7) 87(14.8,-2.7) 88(14.8,2.7) 89(15.6,-2.7) 90(15.6,2.7) 91(16.4,-2.7) 92(16.4,2.7) 93(17.2,-2.7) 94(17.2,2.7) 95(18,-2.7) 96(18,2.7) 97(18.8,-2.7) 98(18.8,2.7) 99(19.6,-2.7) 100(19.6,2.7)
  round 1.35 hole 0.8: MH1(-22.283,-2.9) MH3(22.317,-2.9)
  oval 1.8x1 all layers, no hole: MH2(-22.283,2.9) MH4(22.317,2.9)
  round 0.7 hole 0.6: MH2A(-22.683,2.9) MH2B(-21.883,2.9) MH4A(21.917,2.9) MH4B(22.717,2.9)
  silkscreen extent -29.95,-4.45 29.95,4.45
ABSM-1574 [mm]
  rect 5x3 smd: 1(0,0) 2(11.8,0)
  rect 1.5x1.5 hole 0.7: 1A(2.65,-0.24)
  round 1.5 hole 0.7: 2A(9.15,-0.24)
  silkscreen extent -1.83,-6.4 12.3,6.4
Altium_Logo [mil] "Altium Logo"
  silkscreen extent -352,-81 352,77
B3FS_SWITCH [mm]
  rect 1.6x1.4 smd: 1(4.01,-2.25) 2(-4,-2.25) 3(4.01,2.24) 4(-4,2.24)
  silkscreen extent -3.16,-3.16 3.15,3.15
C3216-1206 [mm]
  rect 1.6x1.8 smd: 1(-1.4,0) 2(1.4,0)
  silkscreen extent -2.6,-1.3 2.6,1.3
CC2012-0805 [mm]
  rect 1.3x1.5 smd: 1(-0.95,0) 2(0.95,0)
  silkscreen extent -1,-0.9 1,0.9
CC4532-1812 [mm]
  rect 1.9x3.4 smd: 1(-1.95,0) 2(1.95,0)
  silkscreen extent -2.3,-1.9 2.3,1.9
DB15-VGA-Female [mm] "High density D sub 15 pin Female connector"
  rect 1.6x1.6 hole 1.1: 1(0,0)
  round 1.6 hole 1.1: 2(2.29,0) 3(4.58,0) 4(6.87,0) 5(9.16,0) 6(-1.4,2.54) 7(0.89,2.54) 8(3.18,2.54) 9(5.47,2.54) 10(7.76,2.54) 11(0,5.08) 12(2.29,5.08) 13(4.58,5.08) 14(6.87,5.08) 15(9.16,5.08)
  round 5 hole 3.3: 16(-7.915,2.54) 17(17.075,2.54)
  silkscreen extent -10.83,-2.65 20.01,19.61
DIP-16-KEY [mm]
  rect 1.5x1.5 hole 0.9: 1(0,0)
  round 1.5 hole 0.9: 2(2.54,0) 3(5.08,0) 4(7.62,0) 5(10.16,0) 6(12.7,0) 7(15.24,0) 8(17.78,0) 9(17.78,7.62) 10(15.24,7.62) 11(12.7,7.62) 12(10.16,7.62) 13(7.62,7.62) 14(5.08,7.62) 15(2.54,7.62) 16(0,7.62)
  silkscreen extent -2.05,-1.59 19.83,9.2
DO214 [mil] "DO-214-AC/SMA; 2 C-Bend Leads; Body 5.3 x 2.6 mm, inc. leads (LxW)"
  rect 85x110 smd: 1(-87.5,0) 2(87.5,0)
  silkscreen extent -90,-78 90,78
DSUB1.9_MALE [mm]
  rect 1.69x1.69 hole 1.1: 1(1.385,-2.84)
  round 1.69 hole 1.1: 2(-1.385,-2.84) 3(-4.155,-2.84) 4(-6.925,-2.84) 5(-9.695,-2.84) 6(0,0) 7(-2.77,0) 8(-5.54,0) 9(-8.31,0)
  round 4.76 hole 3.3: 10(-16.65,-1.42) 11(8.34,-1.42)
  silkscreen extent -19.56,-4.32 11.24,14.08
DSUB1.385-2H9 [mm]
  rect 1.69x1.69 hole 1.1: 1(-5.54,-10.92)
  round 1.69 hole 1.1: 2(-2.77,-10.92) 3(0,-10.92) 4(2.77,-10.92) 5(5.54,-10.92) 6(-4.155,-8.08) 7(-1.385,-8.08) 8(1.385,-8.08) 9(4.155,-8.08)
  round 4.76 hole 3.3: 10(-12.495,-9.5) 11(12.495,-9.5)
  silkscreen extent -15.4,-12.4 15.4,6
HDR1X2 [mm]
  rect 1.5x1.5 hole 0.9: 1(0,0)
  round 1.5 hole 0.9: 2(2.54,0)
  silkscreen extent -1.27,-1.27 3.81,1.27
HDR2X2 [mm]
  rect 1.5x1.5 hole 0.9: 1(0,0)
  round 1.5 hole 0.9: 2(0,2.54) 3(2.54,0) 4(2.54,2.54)
  silkscreen extent -1.27,-1.27 3.81,3.81
HDR2X2_B [mm] "2x2 HDR un-numbered"
  rect 1.5x1.5 hole 0.9: 1(0,0)
  round 1.5 hole 0.9: 2(0,2.54) 3(2.54,0) 4(2.54,2.54)
  silkscreen extent -1.27,-1.27 3.81,3.81
HDR2X5 [mm]
  rect 1.5x1.5 hole 0.9: 1(0,0)
  round 1.5 hole 0.9: 2(0,2.54) 3(2.54,0) 4(2.54,2.54) 5(5.08,0) 6(5.08,2.54) 7(7.62,0) 8(7.62,2.54) 9(10.16,0) 10(10.16,2.54)
  silkscreen extent -1.27,-1.27 11.43,3.81
HDR2X5_LP [mm] "Header, Shrouded, Dual Row, Low Profile Vertical, 10 pins"
  rect 1.5x1.5 hole 0.9: 1(0,0)
  round 1.5 hole 0.9: 2(0,2.54) 3(2.54,0) 4(2.54,2.54) 5(5.08,0) 6(5.08,2.54) 7(7.62,0) 8(7.62,2.54) 9(10.16,0) 10(10.16,2.54)
  silkscreen extent -5.08,-3.18 15.24,5.72
HDR2X7 [mm]
  rect 1.5x1.5 hole 0.9: 1(0,0)
  round 1.5 hole 0.9: 2(0,2.54) 3(2.54,0) 4(2.54,2.54) 5(5.08,0) 6(5.08,2.54) 7(7.62,0) 8(7.62,2.54) 9(10.16,0) 10(10.16,2.54) 11(12.7,0) 12(12.7,2.54) 13(15.24,0) 14(15.24,2.54)
  silkscreen extent -1.27,-1.27 16.51,3.81
HDR2X9 [mm]
  rect 1.5x1.5 hole 0.9: 1(0,0)
  round 1.5 hole 0.9: 2(0,2.54) 3(2.54,0) 4(2.54,2.54) 5(5.08,0) 6(5.08,2.54) 7(7.62,0) 8(7.62,2.54) 9(10.16,0) 10(10.16,2.54) 11(12.7,0) 12(12.7,2.54) 13(15.24,0) 14(15.24,2.54) 15(17.78,0) 16(17.78,2.54) 17(20.32,0) 18(20.32,2.54)
  silkscreen extent -1.27,-1.27 21.59,3.81
HDR2X10 [mm]
  rect 1.5x1.5 hole 0.9: 1(0,0)
  round 1.5 hole 0.9: 2(0,2.54) 3(2.54,0) 4(2.54,2.54) 5(5.08,0) 6(5.08,2.54) 7(7.62,0) 8(7.62,2.54) 9(10.16,0) 10(10.16,2.54) 11(12.7,0) 12(12.7,2.54) 13(15.24,0) 14(15.24,2.54) 15(17.78,0) 16(17.78,2.54) 17(20.32,0) 18(20.32,2.54) 19(22.86,0) 20(22.86,2.54)
  silkscreen extent -1.27,-1.27 24.13,3.81
HDR2X13_CEN_LP [mm] "Header, Shrouded, Dual Row, Low Profile Vertical, 26 pins, Centronics Printer Port pad numbering"
  rect 1.5x1.5 hole 0.9: 1(0,0)
  round 1.5 hole 0.9: 2(2.54,0) 3(5.08,0) 4(7.62,0) 5(10.16,0) 6(12.7,0) 7(15.24,0) 8(17.78,0) 9(20.32,0) 10(22.86,0) 11(25.4,0) 12(27.94,0) 13(30.48,0) 14(0,2.54) 15(2.54,2.54) 16(5.08,2.54) 17(7.62,2.54) 18(10.16,2.54) 19(12.7,2.54) 20(15.24,2.54) 21(17.78,2.54) 22(20.32,2.54) 23(22.86,2.54) 24(25.4,2.54) 25(27.94,2.54) 26(30.48,2.54)
  silkscreen extent -5.08,-3.18 35.56,5.72
KLD-0202 [mm] "PCB Mount DC Power Jack with 2.1mm or 2.5mm center pin"
  oval 2x4.5 all layers, no hole: 1(13.7,0)
  round 1.5 hole 1: 1A(13.7,-1.25) 1B(13.7,1.25) 2A(7.5,-1) 2B(7.5,1) 3A(9.5,-5) 3B(11.5,-5)
  oval 2x4 all layers, no hole: 2(7.5,0)
  oval 4x2 all layers, no hole: 3(10.5,-5)
  silkscreen extent 0,-4.5 14.6,4.5
MCCT-B [mm]
  rect 2x2.2 smd: 1(-1.5,0) 2(1.5,0)
  silkscreen extent -2.3,-1.6 1.8,1.6
MNR34 [mm] "3216x4 Resistor Array"
  rect 1.2x1 smd: 1(-1.575,1.905) 2(-1.575,0.635) 3(-1.575,-0.635) 4(-1.575,-1.905) 5(1.575,-1.905) 6(1.575,-0.635) 7(1.575,0.635) 8(1.575,1.905)
  silkscreen extent -1.67,-2.62 1.55,3.07
NanoBoard1_LOGO [mil] "NanoBoard 1 Logo"
  silkscreen extent -1007,-97 1007,96
POT4MM-2 [mm]
  rect 2x1.3 smd: CCW(-2,-1.15) CW(-2,1.15)
  rect 2x2 smd: W(2,0)
  silkscreen extent -2.5,-2.5 2.5,2.5
PS2-6PIN [mm] "PS2 Connector"
  round 1.6 hole 0.9: 1(-1.25,-8.5) 2(1.25,-8.5) 3(-3.25,-8.5) 4(3.25,-8.5) 5(-3.25,-11) 6(3.25,-11)
  round 3.5 hole 2.3: S(0,-4.75)
  silkscreen extent -7,-12.75 7,0
QC49/SMD [mm]
  rect 5x2 smd: 1(-4.75,0) 2(4.75,0)
  silkscreen extent -6.75,-2.4 5.7,2.4
QSMO_4200 [mm]
  rect 2x2 smd: 1(0,0.4) 2(5.08,0.4) 3(5.08,4.6) 4(0,4.6)
  silkscreen extent -1.19,-1.31 6.22,4.95
RB8/3.5 [mil]
  rect 70x70 hole 27.56: 1(0,60)
  round 70 hole 27.56: 2(0,-60)
  silkscreen extent -160,-160 160,160
"SMD _LED" [mm]
  rect 1.3x1.6 smd: 1(0.95,0) 2(-0.95,0)
  silkscreen extent -2.13,-1.15 2,1.15
SO8_MW/SO8_MN [mm] "S08 Wide / S08 Narrow dual footprint 8 lead Plastic Small Outline"
  rect 0.6x3.2 smd: 1(-1.905,-3.1) 2(-0.635,-3.1) 3(0.635,-3.1) 4(1.905,-3.1) 5(1.905,3.1) 6(0.635,3.1) 7(-0.635,3.1) 8(-1.905,3.1)
  silkscreen extent -2.88,-2.72 2.5,1.1
SO-G3 [mm]
  rect 0.85x1.3 smd: 1(-0.95,-1.1) 2(0.95,-1.1) 3(0,1.1)
  silkscreen extent -1.95,-1.32 1.95,0.3
SO-G5/P.95 [mm]
  rect 0.55x1.45 smd: 1(-0.95,-1.075) 2(0,-1.075) 3(0.95,-1.075) 4(0.95,1.075) 5(-0.95,1.075)
  silkscreen extent -2.42,-2.2 1.65,2.2
SO-G8 [mm]
  rect 0.6x2.2 smd: 1(-1.905,-2.6) 2(-0.635,-2.6) 3(0.635,-2.6) 4(1.905,-2.6) 5(1.905,2.6) 6(0.635,2.6) 7(-0.635,2.6) 8(-1.905,2.6)
  silkscreen extent -2.88,-2.72 2.5,1.1
SO-G14/Y2.2 [mm]
  rect 0.6x2.2 smd: 1(-3.81,-2.625) 2(-2.54,-2.625) 3(-1.27,-2.625) 4(0,-2.625) 5(1.27,-2.625) 6(2.54,-2.625) 7(3.81,-2.625) 8(3.81,2.625) 9(2.54,2.625) 10(1.27,2.625) 11(0,2.625) 12(-1.27,2.625) 13(-2.54,2.625) 14(-3.81,2.625)
  silkscreen extent -4.79,-2.75 4.38,1.12
SO-G16 [mm]
  rect 0.6x2.2 smd: 1(-4.445,-2.6) 2(-3.175,-2.6) 3(-1.905,-2.6) 4(-0.635,-2.6) 5(0.635,-2.6) 6(1.905,-2.6) 7(3.175,-2.6) 8(4.445,-2.6) 9(4.445,2.6) 10(3.175,2.6) 11(1.905,2.6) 12(0.635,2.6) 13(-0.635,2.6) 14(-1.905,2.6) 15(-3.175,2.6) 16(-4.445,2.6)
  silkscreen extent -5.42,-2.72 5,1.1
SO-J32 [mm]
  rect 0.6x2.2 smd: 1(-9.525,-3.6) 2(-8.255,-3.6) 3(-6.985,-3.6) 4(-5.715,-3.6) 5(-4.445,-3.6) 6(-3.175,-3.6) 7(-1.905,-3.6) 8(-0.635,-3.6) 9(0.635,-3.6) 10(1.905,-3.6) 11(3.175,-3.6) 12(4.445,-3.6) 13(5.715,-3.6) 14(6.985,-3.6) 15(8.255,-3.6) 16(9.525,-3.6) 17(9.525,3.6) 18(8.255,3.6) 19(6.985,3.6) 20(5.715,3.6) 21(4.445,3.6) 22(3.175,3.6) 23(1.905,3.6) 24(0.635,3.6) 25(-0.635,3.6) 26(-1.905,3.6) 27(-3.175,3.6) 28(-4.445,3.6) 29(-5.715,3.6) 30(-6.985,3.6) 31(-8.255,3.6) 32(-9.525,3.6)
  silkscreen extent -10.5,-4.19 10.33,4.19
SOIC8 [mm]
  rect 1.5x0.5 smd: 1(0,0) 2(0,-1.27) 3(0,-2.54) 4(0,-3.81) 5(6,-3.81) 6(6,-2.54) 7(6,-1.27) 8(6,0)
  silkscreen extent 1.1,-4.5 4.9,0.7
SOT23_8 [mm]
  rect 1.5x0.35 smd: 1(-1.5,0.975) 2(-1.5,0.325) 3(-1.5,-0.325) 4(-1.5,-0.975) 5(1.5,-0.975) 6(1.5,-0.325) 7(1.5,0.325) 8(1.5,0.975)
  silkscreen extent -0.55,-1.3 0.55,1.3
SSO-G20/P.65 [mm]
  rect 0.4x2.15 smd: 1(-2.925,-3.275) 2(-2.275,-3.275) 3(-1.625,-3.275) 4(-0.975,-3.275) 5(-0.325,-3.275) 6(0.325,-3.275) 7(0.975,-3.275) 8(1.625,-3.275) 9(2.275,-3.275) 10(2.925,-3.275) 11(2.925,3.275) 12(2.275,3.275) 13(1.625,3.275) 14(0.975,3.275) 15(0.325,3.275) 16(-0.325,3.275) 17(-0.975,3.275) 18(-1.625,3.275) 19(-2.275,3.275) 20(-2.925,3.275)
  silkscreen extent -3.8,-3.4 3.75,1.8
ST-3150-5N [mm] "3.5mm Stereo Jack, 5 pin, 8.1mm wide"
  oval 2.7x1.8 all layers, no hole: 1(-0.85,-5.2) 2(1.15,-7.65) 3(-0.85,-11.35) 4(1.15,-13.25) 5(-0.85,-17)
  round 1.2 hole 1: 1A(-1.3,-5.2) 1B(-0.4,-5.2) 2A(0.7,-7.65) 2B(1.6,-7.65) 3A(-1.3,-11.35) 3B(-0.4,-11.35) 4A(0.7,-13.25) 4B(1.6,-13.25) 5A(-1.3,-17) 5B(-0.4,-17)
  silkscreen extent -4.9,-18 3.2,0
TL36WW15050 [mm] "Vertical right angle SPDT switch"
  round 2 hole 1.1: 1(0,0) 2(0,-2.54) 3(0,-5.08) M(0,5.08)
  Top Layer keep-out region: -2.54,1.27 2.54,1.27 2.54,8.509 -2.54,8.509
  Top Layer keep-out region: -2.54,0 -1.27,0 -1.27,1.27 -2.54,1.27
  Top Layer keep-out region: 1.27,0 2.54,0 2.54,1.27 1.27,1.27
  silkscreen extent -2.54,0 2.54,19.56
TO-263 [mm] "D2-PACK SIP-G3/P2.54"
  rect 1x3.4 smd: 1(0,0) 2(2.54,0) 3(5.08,0)
  rect 10.25x8.9 smd: 4(2.54,10.45)
  silkscreen extent -3.1,-3.13 8.2,15
TQ144 [mm] "144-Pin Thin Quad Flat Pack (TQ144)"
  rect 1.6x0.3 smd: 1(-10.6,8.75) 2(-10.6,8.25) 3(-10.6,7.75) 4(-10.6,7.25) 5(-10.6,6.75) 6(-10.6,6.25) 7(-10.6,5.75) 8(-10.6,5.25) 9(-10.6,4.75) 10(-10.6,4.25) 11(-10.6,3.75) 12(-10.6,3.25) 13(-10.6,2.75) 14(-10.6,2.25) 15(-10.6,1.75) 16(-10.6,1.25) 17(-10.6,0.75) 18(-10.6,0.25) 19(-10.6,-0.25) 20(-10.6,-0.75) 21(-10.6,-1.25) 22(-10.6,-1.75) 23(-10.6,-2.25) 24(-10.6,-2.75) 25(-10.6,-3.25) 26(-10.6,-3.75) 27(-10.6,-4.25) 28(-10.6,-4.75) 29(-10.6,-5.25) 30(-10.6,-5.75) 31(-10.6,-6.25) 32(-10.6,-6.75) 33(-10.6,-7.25) 34(-10.6,-7.75) 35(-10.6,-8.25) 36(-10.6,-8.75) 73(10.6,-8.75) 74(10.6,-8.25) 75(10.6,-7.75) 76(10.6,-7.25) 77(10.6,-6.75) 78(10.6,-6.25) 79(10.6,-5.75) 80(10.6,-5.25) 81(10.6,-4.75) 82(10.6,-4.25) 83(10.6,-3.75) 84(10.6,-3.25) 85(10.6,-2.75) 86(10.6,-2.25) 87(10.6,-1.75) 88(10.6,-1.25) 89(10.6,-0.75) 90(10.6,-0.25) 91(10.6,0.25) 92(10.6,0.75) 93(10.6,1.25) 94(10.6,1.75) 95(10.6,2.25) 96(10.6,2.75) 97(10.6,3.25) 98(10.6,3.75) 99(10.6,4.25) 100(10.6,4.75) 101(10.6,5.25) 102(10.6,5.75) 103(10.6,6.25) 104(10.6,6.75) 105(10.6,7.25) 106(10.6,7.75) 107(10.6,8.25) 108(10.6,8.75)
  rect 0.3x1.6 smd: 37(-8.75,-10.6) 38(-8.25,-10.6) 39(-7.75,-10.6) 40(-7.25,-10.6) 41(-6.75,-10.6) 42(-6.25,-10.6) 43(-5.75,-10.6) 44(-5.25,-10.6) 45(-4.75,-10.6) 46(-4.25,-10.6) 47(-3.75,-10.6) 48(-3.25,-10.6) 49(-2.75,-10.6) 50(-2.25,-10.6) 51(-1.75,-10.6) 52(-1.25,-10.6) 53(-0.75,-10.6) 54(-0.25,-10.6) 55(0.25,-10.6) 56(0.75,-10.6) 57(1.25,-10.6) 58(1.75,-10.6) 59(2.25,-10.6) 60(2.75,-10.6) 61(3.25,-10.6) 62(3.75,-10.6) 63(4.25,-10.6) 64(4.75,-10.6) 65(5.25,-10.6) 66(5.75,-10.6) 67(6.25,-10.6) 68(6.75,-10.6) 69(7.25,-10.6) 70(7.75,-10.6) 71(8.25,-10.6) 72(8.75,-10.6) 109(8.75,10.6) 110(8.25,10.6) 111(7.75,10.6) 112(7.25,10.6) 113(6.75,10.6) 114(6.25,10.6) 115(5.75,10.6) 116(5.25,10.6) 117(4.75,10.6) 118(4.25,10.6) 119(3.75,10.6) 120(3.25,10.6) 121(2.75,10.6) 122(2.25,10.6) 123(1.75,10.6) 124(1.25,10.6) 125(0.75,10.6) 126(0.25,10.6) 127(-0.25,10.6) 128(-0.75,10.6) 129(-1.25,10.6) 130(-1.75,10.6) 131(-2.25,10.6) 132(-2.75,10.6) 133(-3.25,10.6) 134(-3.75,10.6) 135(-4.25,10.6) 136(-4.75,10.6) 137(-5.25,10.6) 138(-5.75,10.6) 139(-6.25,10.6) 140(-6.75,10.6) 141(-7.25,10.6) 142(-7.75,10.6) 143(-8.25,10.6) 144(-8.75,10.6)
  round 1 smd paste-0.55 mask+1: FID1(-10.6,-10.6) FID2(10.6,10.6)
  Top Layer keep-out circle w0.2: c10.6,10.6 r1.072
  Top Layer keep-out circle w0.2: c-10.6,-10.6 r1.072
  silkscreen extent -10.72,-9.4 9.4,9.57
TS2.54x10 [mm] "10 way 2.54mm Pitch screw terminal"
  round 1.85 hole 1.1: 1(0,0) 2(0,-2.54) 3(0,-5.08) 4(0,-7.62) 5(0,-10.16) 6(0,-12.7) 7(0,-15.24) 8(0,-17.78) 9(0,-20.32) 10(0,-22.86)
  silkscreen extent -3.35,-24.36 3.25,2.65
TSSO3x5-G8/X.35 [mm]
  rect 0.35x1.5 smd: 1(-0.975,-2.075) 2(-0.325,-2.075) 3(0.325,-2.075) 4(0.975,-2.075) 5(0.975,2.075) 6(0.325,2.075) 7(-0.325,2.075) 8(-0.975,2.075)
  silkscreen extent -1.82,-2.2 1.52,0.92
USOP10 [mm]
  rect 1.5x0.25 smd: 1(-2.5,1) 2(-2.5,0.5) 3(-2.5,0) 4(-2.5,-0.5) 5(-2.5,-1) 6(2.5,-1) 7(2.5,-0.5) 8(2.5,0) 9(2.5,0.5) 10(2.5,1)
  silkscreen extent -1.5,-1.4 1.5,1.4
VO20 [mm] "20-Lead TSOP (VO20)"
  rect 0.3x1.65 smd: 1(-2.925,-2.775) 2(-2.275,-2.775) 3(-1.625,-2.775) 4(-0.975,-2.775) 5(-0.325,-2.775) 6(0.325,-2.775) 7(0.975,-2.775) 8(1.625,-2.775) 9(2.275,-2.775) 10(2.925,-2.775) 11(2.925,2.775) 12(2.275,2.775) 13(1.625,2.775) 14(0.975,2.775) 15(0.325,2.775) 16(-0.325,2.775) 17(-0.975,2.775) 18(-1.625,2.775) 19(-2.275,2.775) 20(-2.925,2.775)
  silkscreen extent -3.75,-2.9 3.3,1.55

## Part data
C1 C5 C9 C15 C16 C21 C22 C23 C24 C25 C26 C27 C30 C35 C38 C39 C46 C48: library part CAP_POLAR, "Polar Capacitor"
C2 C3 C4 C6 C7 C8 C10 C11 C12 C13 C14 C17 C18 C19 C20 C28 C29 C31 C32 C33 C34 C36 C37 C40 C41 C42 C43 C44 C45 C47 C49 C50 C51 C52 C53 C54 C55 C56 C57 C58 C59 C60 C61 C62 C63 C64 C65 C66 C67 C68 C69 C70 C71 C72 C73 C74 C75 C76 C77 C78 C79 C80 C81 C82 C83 C84 C85 C86 C87 C88: library part CAP, "Capacitor"
CR1: "SMD Crystal 20MHz HY-Q"
D1 D2 D3 D4 D5: "Shottky Diode Pair"
D6: "Shottky Diode"
D7: library part BZG03C13, "Zener Diode, 6.2V, 5W"
GJ1 GJ2 GJ3 GJ4 GJ5 GJ6 GJ7 GJ8 JP3: "Header, 2-Pin"
HDR1 HDR2 HDR4 HDR5: "Header, 5-Pin, Dual row"
HDR3: library part "Header 13X2A", "Header, 13-Pin, Dual row"
HDR6 HDR7: library part "Header 5X2", "Header, 5-Pin, Dual row"
HDR8: "Header, 7-Pin, Dual row"
HDR9 HDR10: "Header, 10-Pin, Dual row"
J1: library part "D Connector 9", "Receptacle Assembly, 9 Position, Right Angle"
J2: "Receptacle Assembly, 9 Position, Right Angle"
J3: "Dsub-15 High density VGA Female connetor"
J4 J5: library part PS2-6PIN, "6 Pin Through Hole PS2 Socket (Kycon P/N)"
J6 J7: "Low Voltage Power Supply Connector"
J8 J9: "Board-to-Board, Docking Station, 0.80mm (.031\") Pitch, Shielded Plug, Vertical, Ultra Low Profile, SMT"
J10 J11: "3-Conductor Jack with 2 break contacts (normals) and 2 auxiliary make contacts"
JP1 JP4 JP5 JP6: "Header, 2-Pin, Dual row"
JP2: "Header, 9-Pin, Dual row"
L1: library part INDUCTOR, "Inductor e.g. Farnell 3876895"
LCD1: "16 char * 2 line LCD character display with b/light"
LED0 LED1 LED2 LED3 LED4 LED5 LED6 LED7 LED8 LED9 LED10 LED11 LED12 LED13 LED14 LED15 LED16: library part HSMX-C670, "Typical RED GaAs SMD LED Agilent make"
Q1 Q3 Q4: "N Channel Mosfet"
Q2: "P Channel Mosfet"
R1 R2 R3 R4 R5 R6 R7 R8 R9 R10 R11 R12 R13 R14 R15 R16 R17 R18 R19 R20 R21 R22 R23 R24 R25 R26 R27 R28 R29 R30 R31 R32 R33 R34 R35 R36 R37 R38 R39 R40 R41 R42 R43 R44 R45 R46 R47 R48 R49 R50 R51 R52 R53 R54 R55 R56 R57 R58 R59 R60 R61 R62 R63 R64 R65 R66 R67 R68 R69 R70 R71 R72 R73 R74 R75 R76 R77 R78 R79 R80: library part RES, "Resistor"
RA1 RA2 RA3 RA4 RA5 RA6 RA7 RA8 RA9 RA10 RA11 RA12 RA13 RA14 RA15 RA16 RA17 RA18 RA19 RA20 RA21 RA22 RA23 RA24 RA25 RA26 RA27 RA28 RA29 RA30 RA31 RA32: library part MNR34, "3216x4 Resistor Array"
S1: library part PCB_MOUNT_SWITCH, "SPDT Subminiature Toggle Switch"
S2: "DIP Switch Side actuator long liver Piano Key"
SPKR1: "Megastar Subminiature Transducer"
SW1 SW2 SW3 SW4 SW5 SW6 SW7 SW8 SW9 SW10 SW11 SW12 SW13 SW14 SW15 SW16 SW17: library part B3FS, "SPNA SMD Keyboard Switch"
TS1: "Screw Terminal Strip, 10 Way, 2.54 mm Pitch"
U1: library part MAX3232EUE, "3.0V TO 5.5V, Low-Power, up to 1Mbps, True RS-232 Transceiver Using Four 0.1µF External Capacitor"
U2: "High Speed Can Transceiver"
U3: library part MC74HC00AD, "Quad 2-Input NAND Gate"
U4: library part 74LVC244A, "Octal Buffer/Driver with 3-State Outputs"
U5: "XCF00S Series, Platform Flash In-System Programmable Configuration 3.3V PROM, 1-Megabit, Commercial Grade"
U6: library part M25P10-VMN6, "8 Mbit Flash Serial Prom"
U7: library part M25P20-VMN6, "8 Mbit Flash Serial Prom"
U8: "Spartan-IIE 1.8V FPGA, 144-Pin TQFP, Standard Performance, Commercial Grade"
U9 U10 U11: "5A Low Dropout Possitive Regulators"
U12: library part ICS307-02, "Serial Programmable PLL Oscillator"
U13: "Surface Mount Crystal Oscillator"
U14 U15: "128K x 8 bit Fast Static RAM"
U16: library part SN74AHC1G04DBVR
U17: library part 74LVC245A, "Octal Bus Transceiver with 3-State Outputs"
U19: "8 bit CODEC with 4 wire logic interface"
U20: library part MAX5841, "4 Channel DAC,I2C,2.7V to 5.5V"
U21: library part MAX1037, "4 Channel 8 Bit ADC, I2C interface, 2.7V to 3.6V Supply"
VR1 VR2: library part POT_M, "Potentiometer"

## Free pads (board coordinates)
  round 31.5 / inner round 31.5 / far side round 78.74 hole 39.37 unplated: KP1(725,2900) KP2(2575,2900) KP3(725,1050) KP4(2575,1050)
  round 98.43 hole 196.85 unplated: LP(4248.9,1972.83) LP(6650.47,791.73) LP(6650.47,3508.27)
  round 118.11 hole 129.92 unplated: M1(200,6300) M2(7700,6300) M3(200,200) M4(7700,200) M5(3420,3050) M6(6550,5430) M7(6550,2200)
  round 59.06 hole 31.5: TP(6175,3630) TP(6275,3630)

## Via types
v1: diameter 35.43, hole 19.68, Top Layer to Bottom Layer, 194 vias
v2: diameter 35.43, hole 19.68, Top Layer to Bottom Layer, tented both sides, 169 vias
v3: diameter 50, hole 27.56, Top Layer to Bottom Layer, 5 vias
